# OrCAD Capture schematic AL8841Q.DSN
size Custom; title: AL8841Q, 40V 1.5A STEP-DOWN LED DRIVER; rev: 1.0; note: DS40367 Rev. 1 - 2
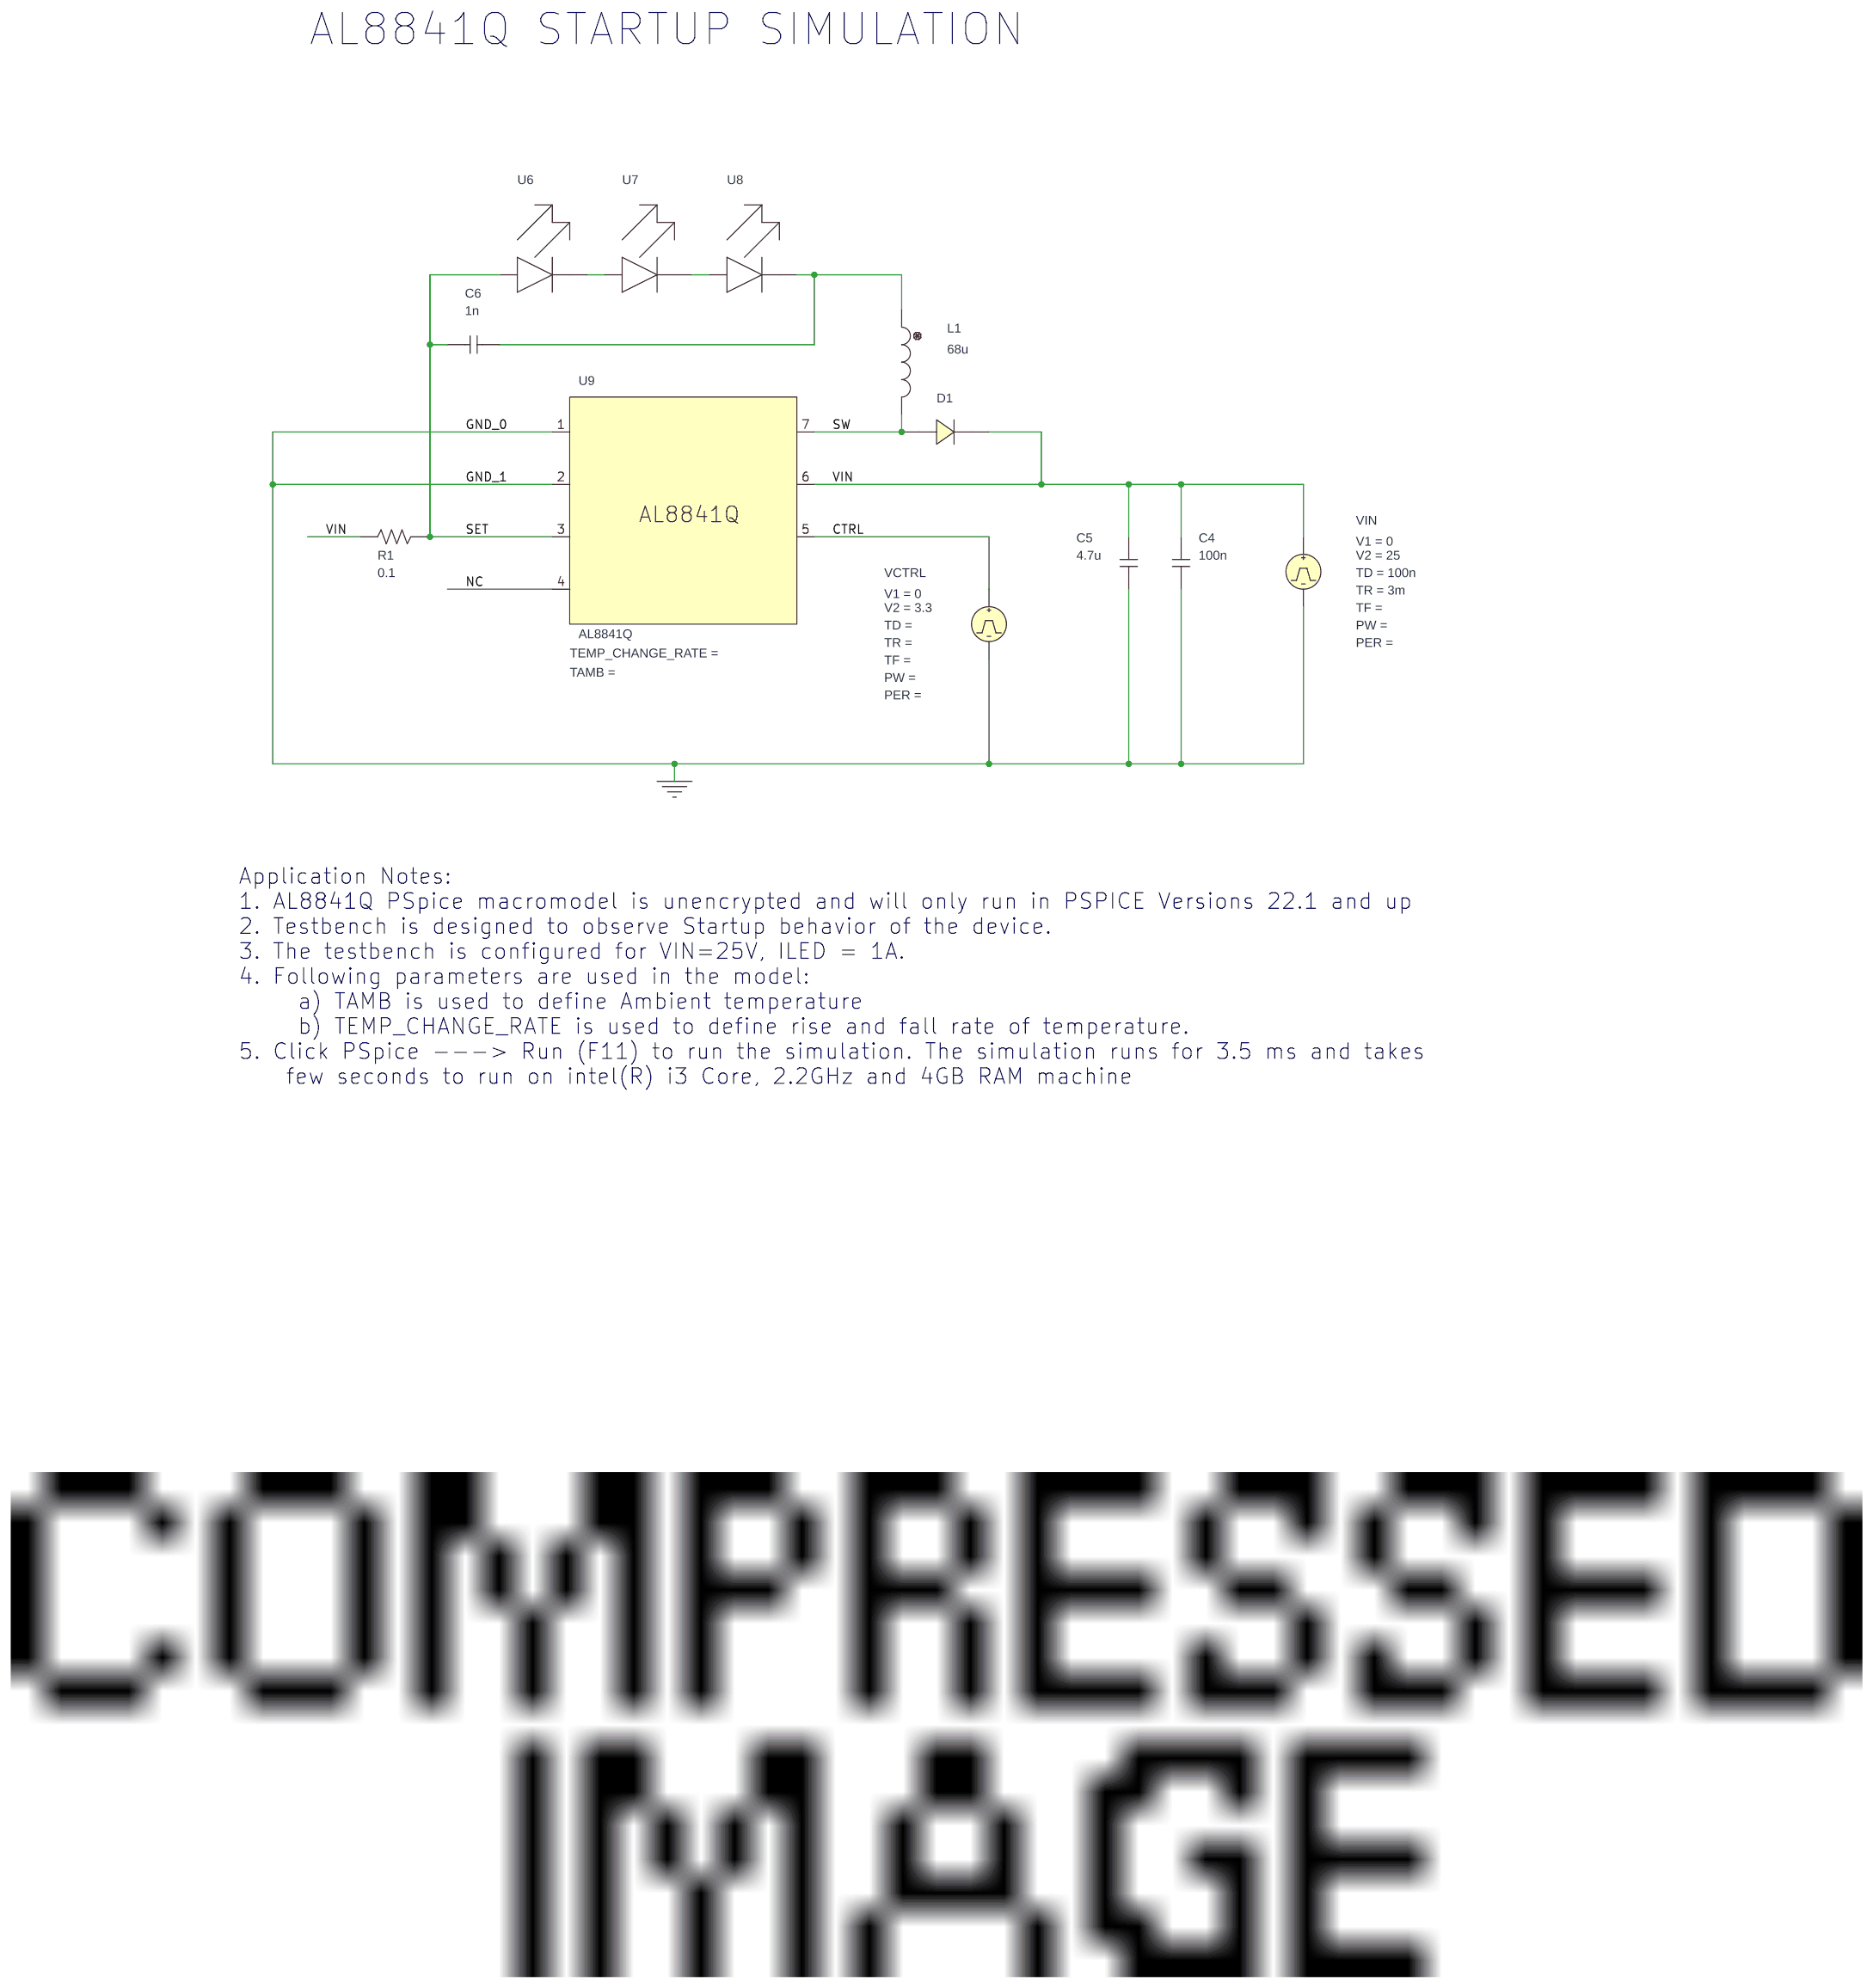
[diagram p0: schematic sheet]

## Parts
C4  100n  [RAD/CK05]
C5  4.7u  [RAD/CK05]
C6  1n  [RAD/CK05]
D1  B240A
L1  68u  [DISC/.350x.175/LS.200x.100/.034]
R1  0.1  [AX/RC05]
U6  _D2_mod
U7  _D2_mod
U8  _D2_mod
U9  AL8841Q
VCTRL  VPULSE
VIN  VPULSE

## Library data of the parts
C4 C5 = C: IC: 0
C6 = C
D1 = B240A
L1 = L: IC: 0
R1 = R
U6-U8 = LEDR
U9 = AL8841Q
VCTRL = VPULSE: V1: 0; V2: 3.3
VIN = VPULSE: TD: 100n; TR: 3m; V1: 0; V2: 25

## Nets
VIN: C4.2 C5.2 D1.1(C) R1.2 U9.6(VIN) VIN.1(+)
0: C4.1 C5.1 U9.1(GND_0) U9.2(GND_1) VCTRL.2(-) VIN.2(-)
CTRL: U9.5(CTRL) VCTRL.1(+)
NC: U9.4(NC)
SET: C6.2 R1.1 U6.1(A) U9.3(SET)
SW: D1.2(A) L1.2 U9.7(SW)
N90786: U6.2(C) U7.1(A)
N90814: U7.2(C) U8.1(A)
N90842: C6.1 L1.1 U8.2(C)

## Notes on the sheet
- AL8841Q STARTUP SIMULATION
- Application Notes:
  1. AL8841Q PSpice macromodel is unencrypted and will only run in PSPICE Versions 22.1 and up
  2. Testbench is designed to observe Startup behavior of the device.
  3. The testbench is configured for VIN=25V, ILED = 1A.
  4. Following parameters are used in the model:
       a) TAMB is used to define Ambient temperature
       b) TEMP_CHANGE_RATE is used to define rise and fall rate of temperature.
  5. Click PSpice ---> Run (F11) to run the simulation. The simulation runs for 3.5 ms and takes
      few seconds to run on intel(R) i3 Core, 2.2GHz and 4GB RAM machine
